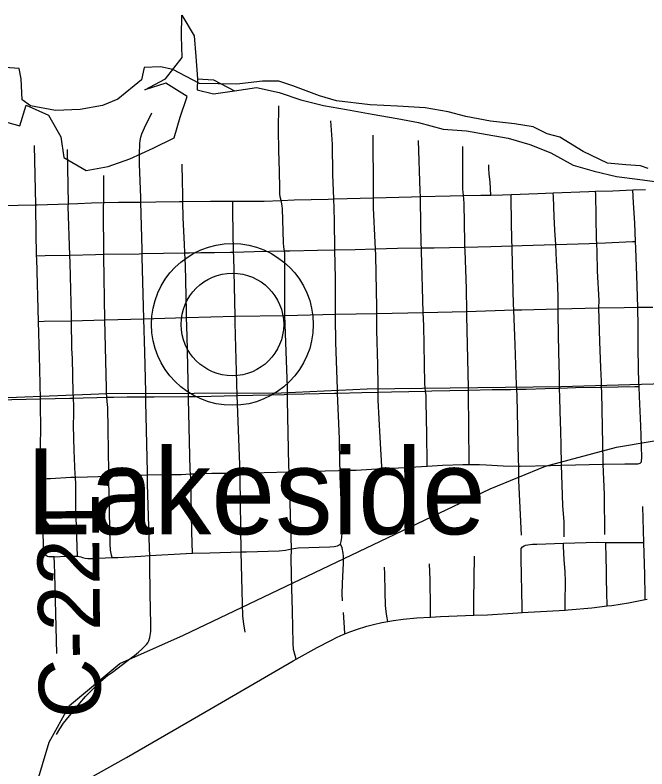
# Model space of a CAD drawing. Extents: x -12 to 34, y 0 to 22.
# Drawn here: x 6.606 to 7.187, y 18.102 to 18.796 of the extents above; entities that cross this region are included whole.
import ezdxf

# ---------------------------------------------------------------- set-up
doc = ezdxf.new("R2010")
doc.units = 0
for name, color, linetype in [('GM_X_Airport_Location_Class_2', 7, 'Continuous'), ('GM_X_Corporation', 7, 'Continuous'), ('GM_X_County_Road', 7, 'Continuous'), ('GM_X_Interstate_Location', 7, 'Continuous'), ('GM_X_Major_Lake', 7, 'Continuous'), ('GM_X_Major_River', 7, 'Continuous'), ('GM_X_Minor_River', 7, 'Continuous'), ('GM_X_Section_Text', 7, 'Continuous'), ('GM_X_Township', 7, 'Continuous'), ('GM_X_Township_Subdivision', 7, 'Continuous')]:
    doc.layers.add(name, color=color, linetype=linetype)

msp = doc.modelspace()

# ---------------------------------------------------------------- linework, layer by layer
at = {"layer": 'GM_X_Airport_Location_Class_2'}
msp.add_lwpolyline([(7.1879, 18.65464), (7.18059, 18.65733), (7.16716, 18.65813), (7.1505, 18.65975), (7.12794, 18.67049), (7.10641, 18.68359), (7.09489, 18.68661), (7.082, 18.69306), (7.0648, 18.69575), (7.04278, 18.69816), (7.02021, 18.70246), (7.00382, 18.70676), (6.9826, 18.71052), (6.95734, 18.71214), (6.93209, 18.71321), (6.9012, 18.71697), (6.88561, 18.72154), (6.8609, 18.73094), (6.84827, 18.73497), (6.83323, 18.73497), (6.80958, 18.73228), (6.7752, 18.73309), (6.75075, 18.74572), (6.7392, 18.7484), (6.72442, 18.7476), (6.72174, 18.73631), (6.69998, 18.71858), (6.686, 18.71267), (6.66559, 18.70918), (6.64275, 18.7081), (6.61992, 18.7124), (6.61213, 18.71805), (6.61105, 18.73739), (6.60944, 18.74679), (6.58768, 18.7484)], dxfattribs=at)
msp.add_lwpolyline([(7.1879, 18.65464), (7.18059, 18.65733), (7.16716, 18.65813), (7.1505, 18.65975), (7.12794, 18.67049), (7.10641, 18.68359), (7.09489, 18.68661), (7.082, 18.69306), (7.0648, 18.69575), (7.04278, 18.69816), (7.02021, 18.70246), (7.00382, 18.70676), (6.9826, 18.71052), (6.95734, 18.71214), (6.93209, 18.71321), (6.9012, 18.71697), (6.88561, 18.72154), (6.8609, 18.73094), (6.84827, 18.73497), (6.83323, 18.73497), (6.80958, 18.73228), (6.7752, 18.73309), (6.75075, 18.74572), (6.7392, 18.7484), (6.72442, 18.7476), (6.72174, 18.73631), (6.69998, 18.71858), (6.686, 18.71267), (6.66559, 18.70918), (6.64275, 18.7081), (6.61992, 18.7124), (6.61213, 18.71805), (6.61105, 18.73739), (6.60944, 18.74679), (6.58768, 18.7484)], dxfattribs=at)
at = {"layer": 'GM_X_Corporation'}
for points in [[(4.21516, 16.89608), (4.31222, 16.96474), (4.74688, 17.31604), (5.03809, 17.55354), (5.18709, 17.66982), (5.65945, 18.04091), (6.05453, 18.35511), (6.09781, 18.38665), (6.1312, 18.40211), (6.16953, 18.40953), (6.55349, 18.44232), (6.69012, 18.44788), (6.85026, 18.4485), (6.9294, 18.45221), (7.10746, 18.45407), (7.25585, 18.4584), (7.28615, 18.45159), (7.37827, 18.44726), (7.7344, 18.45716)], [(5.81508, 17.10766), (6.21975, 17.27361), (6.42432, 17.35397), (6.50615, 17.4016), (6.55673, 17.45964), (6.585, 17.51471), (6.60508, 17.56754), (6.61624, 17.62558), (6.61996, 17.67395), (6.61773, 18.0624), (6.63707, 18.12714), (6.65567, 18.16062), (6.70179, 18.19932), (6.76056, 18.22536), (7.04254, 18.36006), (7.09324, 18.38108), (7.15878, 18.3984), (7.22061, 18.40892), (7.27873, 18.40706), (7.57179, 18.3347), (7.6466, 18.33222), (7.73625, 18.33717), (7.85249, 18.35139), (8.03302, 18.37675)]]:
    msp.add_lwpolyline(points, dxfattribs=at)
at = {"layer": 'GM_X_Interstate_Location'}
for radius in [0.0744, 0.04716]:
    msp.add_circle((6.80544, 18.51131), radius, dxfattribs=at)
at = {"layer": 'GM_X_Major_Lake'}
for points in [[(6.86405, 18.20332), (6.8833, 18.2141), (6.89609, 18.22069), (6.9018, 18.22354), (6.90739, 18.22603), (6.9088, 18.2266), (6.91348, 18.22852), (6.91957, 18.23063), (6.92901, 18.23361), (6.93534, 18.23535), (6.94292, 18.23709), (6.94824, 18.2381), (6.95365, 18.23892), (6.96252, 18.24008), (6.97493, 18.24128), (6.9876, 18.242), (6.99668, 18.24251), (7.02732, 18.24377), (7.04012, 18.24429), (7.06802, 18.24598), (7.07183, 18.2462), (7.11155, 18.24858), (7.11417, 18.24874), (7.13582, 18.25063), (7.15019, 18.25238), (7.15428, 18.25288), (7.16959, 18.25536), (7.18508, 18.25819), (7.18677, 18.25851)], [(6.65922, 18.08561), (6.70793, 18.11308), (6.78602, 18.15808), (6.86128, 18.20177), (6.86405, 18.20332)]]:
    msp.add_lwpolyline(points, dxfattribs=at)
at = {"layer": 'GM_X_Major_River'}
for p, q in [((6.62461, 18.62131), (6.62348, 18.67589)), ((6.65458, 18.62239), (6.65386, 18.6721)), ((7.17353, 18.63503), (7.18535, 18.63547)), ((6.89874, 18.62674), (6.93514, 18.6278)), ((6.59471, 18.6208), (6.60833, 18.62101)), ((6.60833, 18.62101), (6.62461, 18.62131)), ((6.72255, 18.57649), (6.76178, 18.57711)), ((6.98098, 18.52232), (7.02089, 18.52336)), ((7.02089, 18.52336), (7.06422, 18.52468)), ((7.10509, 18.52569), (7.14253, 18.52664)), ((7.17832, 18.52712), (7.1922, 18.52723)), ((6.68808, 18.51548), (6.72391, 18.51638)), ((6.76327, 18.51775), (6.8079, 18.51882)), ((6.8079, 18.51882), (6.85377, 18.51966)), ((6.85377, 18.51966), (6.90015, 18.52074)), ((6.90015, 18.52074), (6.93824, 18.52149)), ((6.93824, 18.52149), (6.98098, 18.52232)), ((6.65752, 18.51477), (6.68808, 18.51548)), ((6.58207, 18.4419), (6.62904, 18.4429)), ((6.81248, 18.37454), (6.80986, 18.44596)), ((7.10802, 18.38189), (7.14644, 18.38265)), ((7.18386, 18.31069), (7.18272, 18.34391))]:
    msp.add_line(p, q, dxfattribs=at)
for points in [[(6.85037, 18.62537), (6.84949, 18.62855), (6.84905, 18.63161), (6.84892, 18.63659), (6.84872, 18.65231), (6.84812, 18.67127), (6.84791, 18.69021), (6.84807, 18.71227)], [(6.72129, 18.62392), (6.72118, 18.628), (6.72001, 18.65881), (6.71991, 18.66814), (6.72022, 18.67744), (6.72054, 18.68052), (6.72116, 18.68354), (6.72201, 18.68651), (6.72457, 18.69216), (6.73145, 18.70608)], [(6.89874, 18.62674), (6.89775, 18.64924), (6.89746, 18.67707), (6.89605, 18.69865)], [(6.93514, 18.6278), (6.93504, 18.63475), (6.93475, 18.68552)], [(6.97827, 18.62901), (6.97815, 18.63386), (6.9766, 18.68044)], [(7.01799, 18.62981), (7.01761, 18.63296), (7.01748, 18.63547), (7.01733, 18.67496)], [(6.75989, 18.62448), (6.75984, 18.6309), (6.75958, 18.64324), (6.75915, 18.65868)], [(7.04296, 18.63038), (7.04273, 18.63619), (7.04248, 18.64242), (7.04144, 18.64945), (7.04111, 18.65507), (7.04124, 18.65827)], [(6.6871, 18.62349), (6.68709, 18.62998), (6.68713, 18.64824)], [(7.1005, 18.63234), (7.13335, 18.63363), (7.13949, 18.63383)], [(7.13949, 18.63383), (7.15539, 18.63437), (7.17353, 18.63503)], [(7.14053, 18.58602), (7.14039, 18.58943), (7.13954, 18.63103), (7.13949, 18.63383)], [(7.17607, 18.58764), (7.17561, 18.6046), (7.17432, 18.62316), (7.17353, 18.63503)], [(6.93514, 18.6278), (6.97, 18.62884), (6.97827, 18.62901)], [(6.937, 18.58088), (6.93676, 18.58675), (6.93534, 18.61859), (6.93514, 18.6278)], [(6.97827, 18.62901), (7.00564, 18.62957), (7.01799, 18.62981)], [(6.97926, 18.58166), (6.9791, 18.58531), (6.97832, 18.62487), (6.97827, 18.62901)], [(7.01799, 18.62981), (7.03394, 18.63013), (7.04296, 18.63038)], [(7.01926, 18.58239), (7.01909, 18.58662), (7.01847, 18.62264), (7.01822, 18.6268), (7.01799, 18.62981)], [(7.04296, 18.63038), (7.05379, 18.63068), (7.06166, 18.63095)], [(7.06166, 18.63095), (7.08631, 18.63179), (7.1005, 18.63234)], [(7.06257, 18.58353), (7.06247, 18.58747), (7.06176, 18.62582), (7.06172, 18.62816), (7.06166, 18.63095)], [(7.10285, 18.58495), (7.10193, 18.59817), (7.10137, 18.61056), (7.10064, 18.62866), (7.1005, 18.63234)], [(6.62461, 18.62131), (6.62603, 18.62133), (6.65458, 18.62239)], [(6.62542, 18.57443), (6.62467, 18.61813), (6.62461, 18.62131)], [(6.65589, 18.57515), (6.65456, 18.61985), (6.65458, 18.62239)], [(6.65458, 18.62239), (6.66335, 18.62269), (6.67572, 18.62325), (6.6871, 18.62349)], [(6.6873, 18.57588), (6.68699, 18.61689), (6.68696, 18.6202), (6.6871, 18.62349)], [(6.6871, 18.62349), (6.70071, 18.62378), (6.71949, 18.62387), (6.72129, 18.62392)], [(6.72129, 18.62392), (6.73513, 18.62406), (6.7569, 18.62445), (6.75989, 18.62448)], [(6.72255, 18.57649), (6.72249, 18.58022), (6.72129, 18.62392)], [(6.75989, 18.62448), (6.7852, 18.62474), (6.80582, 18.62468)], [(6.76178, 18.57711), (6.76145, 18.58504), (6.76012, 18.60935), (6.75989, 18.62448)], [(6.80582, 18.62468), (6.83479, 18.62484), (6.85037, 18.62537)], [(6.80656, 18.57787), (6.80589, 18.61493), (6.80582, 18.62468)], [(6.85037, 18.62537), (6.86223, 18.62579), (6.89336, 18.62656), (6.89874, 18.62674)], [(6.85332, 18.57892), (6.85283, 18.58232), (6.8525, 18.58682), (6.85154, 18.61768), (6.8513, 18.62001), (6.85099, 18.62226), (6.85037, 18.62537)], [(6.89966, 18.57992), (6.89958, 18.58132), (6.89927, 18.60602), (6.89912, 18.61837), (6.89874, 18.62674)], [(7.10285, 18.58495), (7.13354, 18.58567), (7.14053, 18.58602)], [(7.14053, 18.58602), (7.14842, 18.58641), (7.17323, 18.58751), (7.17607, 18.58764)], [(7.14253, 18.52664), (7.14263, 18.53344), (7.14132, 18.56019), (7.14078, 18.57812), (7.14053, 18.58602)], [(7.17832, 18.52712), (7.17745, 18.55628), (7.17653, 18.58108), (7.17607, 18.58764)], [(6.80656, 18.57787), (6.82558, 18.57848), (6.85332, 18.57892)], [(6.85332, 18.57892), (6.85828, 18.57903), (6.88364, 18.57958), (6.89966, 18.57992)], [(6.85377, 18.51966), (6.85376, 18.57308), (6.85356, 18.57619), (6.85332, 18.57892)], [(6.89966, 18.57992), (6.91819, 18.58032), (6.937, 18.58088)], [(6.90015, 18.52074), (6.90034, 18.55362), (6.89966, 18.57992)], [(6.937, 18.58088), (6.95712, 18.58147), (6.97926, 18.58166)], [(6.93824, 18.52149), (6.93828, 18.52722), (6.93774, 18.55808), (6.93719, 18.5749), (6.937, 18.58088)], [(6.97926, 18.58166), (6.99084, 18.58171), (7.01926, 18.58239)], [(6.98098, 18.52232), (6.97939, 18.57869), (6.97926, 18.58166)], [(7.01926, 18.58239), (7.04313, 18.58291), (7.06257, 18.58353)], [(7.02089, 18.52336), (7.0207, 18.54413), (7.01938, 18.57947), (7.01926, 18.58239)], [(7.06257, 18.58353), (7.07198, 18.58383), (7.10212, 18.58493), (7.10285, 18.58495)], [(7.06422, 18.52468), (7.06397, 18.5301), (7.0626, 18.58045), (7.06257, 18.58353)], [(7.10509, 18.52569), (7.10506, 18.53698), (7.10432, 18.55462), (7.1034, 18.57005), (7.10285, 18.58495)], [(6.62542, 18.57443), (6.63341, 18.57462), (6.65589, 18.57515)], [(6.62706, 18.51417), (6.62547, 18.57156), (6.62542, 18.57443)], [(6.65589, 18.57515), (6.67956, 18.57572), (6.6873, 18.57588)], [(6.65752, 18.51477), (6.65745, 18.51883), (6.65614, 18.56812), (6.65589, 18.57515)], [(6.6873, 18.57588), (6.71973, 18.57641), (6.72255, 18.57649)], [(6.68808, 18.51548), (6.68732, 18.5737), (6.6873, 18.57588)], [(6.72391, 18.51638), (6.72254, 18.57315), (6.72255, 18.57649)], [(6.76178, 18.57711), (6.76586, 18.57718), (6.77651, 18.57737), (6.78883, 18.57755), (6.80353, 18.57782), (6.80656, 18.57787)], [(6.76327, 18.51775), (6.76311, 18.52339), (6.76228, 18.56542), (6.76178, 18.57711)], [(6.8079, 18.51882), (6.80663, 18.57381), (6.80656, 18.57787)], [(7.02249, 18.4508), (7.02247, 18.45317), (7.02099, 18.51917), (7.02089, 18.52336)], [(7.06422, 18.52468), (7.07153, 18.52485), (7.10509, 18.52569)], [(7.06686, 18.45167), (7.06656, 18.4559), (7.06539, 18.49249), (7.06422, 18.52468)], [(7.10636, 18.45264), (7.10617, 18.46385), (7.10562, 18.48626), (7.10543, 18.50188), (7.10506, 18.52173), (7.10509, 18.52569)], [(7.14253, 18.52664), (7.16556, 18.52702), (7.17832, 18.52712)], [(7.14499, 18.45376), (7.14477, 18.45904), (7.14417, 18.47151), (7.14333, 18.49574), (7.14253, 18.52664)], [(7.1794, 18.45416), (7.1793, 18.4576), (7.17893, 18.47138), (7.17857, 18.48958), (7.17856, 18.51089), (7.17835, 18.52526), (7.17832, 18.52712)], [(6.72391, 18.51638), (6.73331, 18.51664), (6.76327, 18.51775)], [(6.72589, 18.4448), (6.72576, 18.44928), (6.72502, 18.48594), (6.72391, 18.51638)], [(6.76494, 18.44509), (6.76378, 18.50069), (6.76327, 18.51775)], [(6.80986, 18.44596), (6.80825, 18.50113), (6.80793, 18.51332), (6.8079, 18.51882)], [(6.85611, 18.44706), (6.85598, 18.45343), (6.85377, 18.51966)], [(6.90214, 18.44811), (6.90199, 18.45179), (6.90043, 18.49487), (6.90018, 18.51733), (6.90015, 18.52074)], [(6.93957, 18.44899), (6.93954, 18.45491), (6.93923, 18.47429), (6.93826, 18.50614), (6.93824, 18.52149)], [(6.98306, 18.45007), (6.98284, 18.45285), (6.98255, 18.45694), (6.98154, 18.51028), (6.98098, 18.52232)], [(6.62706, 18.51417), (6.63226, 18.51427), (6.65752, 18.51477)], [(6.62904, 18.4429), (6.62841, 18.46995), (6.62799, 18.4821), (6.62706, 18.51417)], [(6.65945, 18.44353), (6.65913, 18.44861), (6.65837, 18.47996), (6.65789, 18.48911), (6.65752, 18.51477)], [(6.6901, 18.44428), (6.6898, 18.44825), (6.68959, 18.45282), (6.68808, 18.51548)], [(7.10636, 18.45264), (7.12087, 18.45319), (7.14366, 18.45374), (7.14499, 18.45376)], [(7.14499, 18.45376), (7.16019, 18.45393), (7.17544, 18.45411), (7.1794, 18.45416)], [(7.14644, 18.38265), (7.14635, 18.38506), (7.14513, 18.44894), (7.14499, 18.45376)], [(7.18111, 18.38434), (7.18155, 18.38499), (7.18171, 18.38584), (7.18189, 18.38871), (7.18151, 18.39972), (7.18114, 18.41791), (7.17967, 18.44493), (7.1794, 18.45416)], [(6.80986, 18.44596), (6.85297, 18.447), (6.85611, 18.44706)], [(6.85611, 18.44706), (6.87141, 18.44739), (6.89945, 18.44802), (6.90214, 18.44811)], [(6.85757, 18.37577), (6.85733, 18.38147), (6.85617, 18.44164), (6.85611, 18.44706)], [(6.90214, 18.44811), (6.92444, 18.44857), (6.93957, 18.44899)], [(6.90439, 18.37711), (6.90426, 18.38355), (6.90383, 18.40596), (6.90214, 18.44811)], [(6.94284, 18.37875), (6.94278, 18.38076), (6.94124, 18.40737), (6.93954, 18.44153), (6.93957, 18.44899)], [(6.93957, 18.44899), (6.95169, 18.44933), (6.96762, 18.44969), (6.98306, 18.45007)], [(6.98306, 18.45007), (6.98875, 18.45022), (7.02183, 18.45079), (7.02249, 18.4508)], [(6.98462, 18.38103), (6.98457, 18.38431), (6.98415, 18.41015), (6.98377, 18.44002), (6.98348, 18.44584), (6.98306, 18.45007)], [(7.02307, 18.38242), (7.02305, 18.38513), (7.02246, 18.44791), (7.02249, 18.4508)], [(7.02249, 18.4508), (7.04425, 18.45134), (7.06134, 18.45153), (7.06686, 18.45167)], [(7.06686, 18.45167), (7.07567, 18.4519), (7.09294, 18.45245), (7.10636, 18.45264)], [(7.0687, 18.38096), (7.06861, 18.38667), (7.06722, 18.44536), (7.06686, 18.45167)], [(7.10802, 18.38189), (7.10772, 18.40052), (7.10746, 18.41276), (7.10682, 18.43149), (7.10654, 18.444), (7.10636, 18.45264)], [(6.62997, 18.36939), (6.62942, 18.37383), (6.62903, 18.37899), (6.62893, 18.38484), (6.62903, 18.40312), (6.62916, 18.41277), (6.62904, 18.44036), (6.62904, 18.4429)], [(6.62904, 18.4429), (6.65591, 18.44347), (6.65945, 18.44353)], [(6.66103, 18.37085), (6.66087, 18.37339), (6.65993, 18.39533), (6.65936, 18.41844), (6.6596, 18.42868), (6.65976, 18.43621), (6.65945, 18.44353)], [(6.65945, 18.44353), (6.66833, 18.44372), (6.68072, 18.44396), (6.6901, 18.44428)], [(6.6901, 18.44428), (6.69619, 18.44442), (6.70854, 18.44463), (6.72589, 18.4448)], [(6.69177, 18.37185), (6.69166, 18.37566), (6.69119, 18.41491), (6.69078, 18.43494), (6.6904, 18.4404), (6.6901, 18.44428)], [(6.72589, 18.4448), (6.73339, 18.44487), (6.76494, 18.44509)], [(6.7273, 18.37285), (6.72722, 18.37564), (6.72595, 18.43975), (6.72589, 18.4448)], [(6.76494, 18.44509), (6.77397, 18.44515), (6.80986, 18.44596)], [(6.76689, 18.37376), (6.76672, 18.37756), (6.76499, 18.44301), (6.76494, 18.44509)], [(7.14644, 18.38265), (7.14734, 18.38263), (7.1663, 18.38303), (7.17835, 18.38321), (7.1794, 18.38333), (7.18034, 18.38366), (7.18111, 18.38434)], [(6.90439, 18.37711), (6.91931, 18.37728), (6.94284, 18.37875)], [(6.94284, 18.37875), (6.9582, 18.37955), (6.98462, 18.38103)], [(6.98462, 18.38103), (6.99855, 18.38181), (7.0172, 18.38241), (7.02307, 18.38242)], [(7.02307, 18.38242), (7.03273, 18.38242), (7.03893, 18.38201), (7.05445, 18.38112), (7.0687, 18.38096)], [(7.0687, 18.38096), (7.06998, 18.38094), (7.09794, 18.38158), (7.10802, 18.38189)], [(7.0714, 18.31759), (7.06899, 18.3678), (7.06884, 18.37497), (7.0687, 18.38096)], [(7.11059, 18.31593), (7.11066, 18.32982), (7.10943, 18.34479), (7.10857, 18.3637), (7.10802, 18.38189)], [(7.14793, 18.31822), (7.14753, 18.35477), (7.14644, 18.38265)], [(6.62997, 18.36939), (6.635, 18.3696), (6.63812, 18.36973), (6.65678, 18.37072), (6.66103, 18.37085)], [(6.66103, 18.37085), (6.67208, 18.3712), (6.69177, 18.37185)], [(6.66308, 18.29814), (6.66155, 18.34294), (6.66133, 18.36445), (6.66103, 18.37085)], [(6.69177, 18.37185), (6.69998, 18.37208), (6.7273, 18.37285)], [(6.69472, 18.29678), (6.69431, 18.29903), (6.69344, 18.30373), (6.69292, 18.30948), (6.69187, 18.3687), (6.69177, 18.37185)], [(6.7273, 18.37285), (6.74295, 18.37321), (6.75835, 18.37341), (6.76689, 18.37376)], [(6.72946, 18.29879), (6.72914, 18.3054), (6.72743, 18.36462), (6.7273, 18.37285)], [(6.76689, 18.37376), (6.77286, 18.37396), (6.78641, 18.37435), (6.80888, 18.37451), (6.81248, 18.37454)], [(6.76885, 18.30092), (6.76818, 18.32013), (6.76743, 18.35391), (6.76707, 18.36984), (6.76689, 18.37376)], [(6.81248, 18.37454), (6.83479, 18.37507), (6.85757, 18.37577)], [(6.81361, 18.302), (6.81265, 18.3697), (6.81248, 18.37454)], [(6.85757, 18.37577), (6.87231, 18.37623), (6.89077, 18.37668), (6.90314, 18.3771), (6.90439, 18.37711)], [(6.8597, 18.30489), (6.85821, 18.35769), (6.85757, 18.37577)], [(6.90486, 18.30931), (6.9056, 18.31152), (6.90609, 18.31544), (6.90633, 18.3195), (6.90608, 18.33548), (6.90444, 18.37153), (6.90439, 18.37711)], [(6.64152, 18.29745), (6.63822, 18.29745), (6.6366, 18.29766), (6.63551, 18.29799), (6.63456, 18.29856), (6.63343, 18.29953), (6.63261, 18.30044), (6.63198, 18.30153), (6.63166, 18.30271), (6.63159, 18.3049), (6.63088, 18.36028), (6.63047, 18.36546), (6.62997, 18.36939)], [(6.8597, 18.30489), (6.86582, 18.30571), (6.89505, 18.30685), (6.89909, 18.30698), (6.90204, 18.30759), (6.90486, 18.30931)], [(6.90678, 18.257), (6.90649, 18.26353), (6.90659, 18.27291), (6.90757, 18.2917), (6.90752, 18.29793), (6.90734, 18.30104), (6.90634, 18.30587), (6.90486, 18.30931)], [(7.07105, 18.30534), (7.07233, 18.30663), (7.07371, 18.30761), (7.07508, 18.30828), (7.07722, 18.30872), (7.08143, 18.30906), (7.08529, 18.30926), (7.10979, 18.30997)], [(7.10979, 18.30997), (7.14108, 18.31088), (7.14881, 18.31084)], [(7.11155, 18.24858), (7.11158, 18.25536), (7.11169, 18.27477), (7.11147, 18.28415), (7.11061, 18.29482), (7.10992, 18.30742), (7.10979, 18.30997)], [(7.14881, 18.31084), (7.1774, 18.31069), (7.18386, 18.31069)], [(7.15019, 18.25238), (7.15001, 18.25608), (7.14978, 18.26091), (7.14901, 18.30075), (7.14891, 18.30586), (7.14881, 18.31084)], [(7.18508, 18.25819), (7.18503, 18.2619), (7.18475, 18.28088), (7.18386, 18.31069)], [(6.72946, 18.29879), (6.76299, 18.30069), (6.76885, 18.30092)], [(6.76885, 18.30092), (6.7846, 18.30123), (6.81361, 18.302)], [(6.81361, 18.302), (6.81842, 18.30224), (6.8485, 18.303), (6.85427, 18.30358), (6.8597, 18.30489)], [(6.81732, 18.22819), (6.8159, 18.23587), (6.81503, 18.24295), (6.81443, 18.26618), (6.81361, 18.302)], [(6.86405, 18.20332), (6.86316, 18.20689), (6.86177, 18.21243), (6.8613, 18.21811), (6.86073, 18.24763), (6.86021, 18.26878), (6.85952, 18.29552), (6.8597, 18.30489)], [(7.07183, 18.2462), (7.07176, 18.25083), (7.0711, 18.29554), (7.07106, 18.30288), (7.07105, 18.30534)], [(6.64152, 18.29745), (6.65289, 18.29802), (6.66308, 18.29814)], [(6.644, 18.20869), (6.64225, 18.2819), (6.64188, 18.29098), (6.64152, 18.29745)], [(6.6436, 18.13395), (6.64672, 18.13934), (6.65027, 18.14443), (6.6583, 18.15472), (6.66517, 18.16302), (6.67027, 18.16893), (6.67729, 18.17611), (6.6824, 18.18122), (6.6907, 18.18841), (6.69506, 18.19158), (6.71235, 18.20472), (6.71547, 18.20688), (6.71912, 18.20984), (6.72214, 18.21267), (6.72422, 18.21475), (6.72527, 18.21571), (6.72644, 18.21698), (6.72752, 18.2185), (6.72844, 18.22021), (6.72949, 18.22325), (6.73028, 18.22879), (6.73045, 18.23518), (6.7298, 18.26375), (6.7296, 18.29057), (6.72946, 18.29879)], [(6.66308, 18.29814), (6.66452, 18.2979), (6.66599, 18.29756), (6.66774, 18.29694), (6.67, 18.29637), (6.67255, 18.29615), (6.6768, 18.29608), (6.69472, 18.29678)], [(6.69472, 18.29678), (6.70021, 18.297), (6.72121, 18.29805), (6.72946, 18.29879)], [(7.02732, 18.24377), (7.02736, 18.24741), (7.02745, 18.25751), (7.02815, 18.29806)], [(6.94824, 18.2381), (6.9474, 18.2428), (6.94671, 18.24728), (6.94636, 18.2528), (6.94586, 18.26543), (6.94548, 18.28174), (6.94538, 18.28789)], [(6.9876, 18.242), (6.9876, 18.24622), (6.9876, 18.25077), (6.98741, 18.27669), (6.98664, 18.29115)], [(6.9088, 18.2266), (6.90844, 18.23238), (6.90754, 18.24644)]]:
    msp.add_lwpolyline(points, dxfattribs=at)
at = {"layer": 'GM_X_Minor_River'}
for points in [[(6.59087, 18.69938), (6.60985, 18.69406), (6.61592, 18.71306), (6.63641, 18.70395), (6.6478, 18.68381), (6.65046, 18.66481), (6.67096, 18.65304), (6.69107, 18.65646), (6.71118, 18.66368), (6.73243, 18.67356), (6.75179, 18.68306), (6.75748, 18.70206), (6.76393, 18.72105), (6.74419, 18.73321), (6.72484, 18.72713), (6.74381, 18.73739), (6.75937, 18.75677), (6.75861, 18.77652), (6.75898, 18.7959), (6.77037, 18.77691), (6.77189, 18.75791), (6.77341, 18.73739), (6.77303, 18.72725)], [(6.59087, 18.69938), (6.60985, 18.69406), (6.61592, 18.71306), (6.63641, 18.70395), (6.6478, 18.68381), (6.65046, 18.66481), (6.67096, 18.65304), (6.69107, 18.65646), (6.71118, 18.66368), (6.73243, 18.67356), (6.75179, 18.68306), (6.75748, 18.70206), (6.76393, 18.72105), (6.74419, 18.73321), (6.72484, 18.72713), (6.74381, 18.73739), (6.75937, 18.75677), (6.75861, 18.77652), (6.75898, 18.7959), (6.77037, 18.77691), (6.77189, 18.75791), (6.77341, 18.73739), (6.78814, 18.73626)], [(6.78814, 18.73626), (6.80738, 18.72626), (6.82753, 18.72931), (6.84844, 18.72475), (6.86822, 18.71791), (6.88913, 18.71259), (6.91042, 18.70918), (6.934, 18.70462), (6.95681, 18.70082), (6.97659, 18.69702), (6.9994, 18.69094), (7.0207, 18.68943), (7.0397, 18.68601), (7.0591, 18.68259), (7.07887, 18.67689), (7.09827, 18.66929), (7.1188, 18.6579), (7.13819, 18.6522), (7.15872, 18.64726), (7.17812, 18.64498), (7.19865, 18.64233)], [(6.77303, 18.72725), (6.78798, 18.7236), (6.80738, 18.72626), (6.82753, 18.72931), (6.84844, 18.72475), (6.86822, 18.71791), (6.88913, 18.71259), (6.91042, 18.70918), (6.934, 18.70462), (6.95681, 18.70082), (6.97659, 18.69702), (6.9994, 18.69094), (7.0207, 18.68943), (7.0397, 18.68601), (7.0591, 18.68259), (7.07887, 18.67689), (7.09827, 18.66929), (7.1188, 18.6579), (7.13819, 18.6522), (7.15872, 18.64726), (7.17812, 18.64498), (7.19865, 18.64233)]]:
    msp.add_lwpolyline(points, dxfattribs=at)
at = {"layer": 'GM_X_Township'}
for points in [[(6.86405, 18.20332), (6.8833, 18.2141), (6.89609, 18.22069), (6.9018, 18.22354), (6.90739, 18.22603), (6.9088, 18.2266), (6.91348, 18.22852), (6.91957, 18.23063), (6.92901, 18.23361), (6.93534, 18.23535), (6.94292, 18.23709), (6.94824, 18.2381), (6.95365, 18.23892), (6.96252, 18.24008), (6.97493, 18.24128), (6.9876, 18.242), (6.99668, 18.24251), (7.02732, 18.24377), (7.04012, 18.24429), (7.06802, 18.24598), (7.07183, 18.2462), (7.11155, 18.24858), (7.11417, 18.24874), (7.13582, 18.25063), (7.15019, 18.25238), (7.15428, 18.25288), (7.16959, 18.25536), (7.18508, 18.25819), (7.18677, 18.25851)], [(6.60709, 18.05699), (6.65922, 18.08561), (6.70793, 18.11308), (6.78602, 18.15808), (6.86128, 18.20177), (6.86405, 18.20332)]]:
    msp.add_lwpolyline(points, dxfattribs=at)
at = {"layer": 'GM_X_Township_Subdivision'}
msp.add_line((6.80544, 18.51131), (6.80544, 18.51131), dxfattribs=at)

# ---------------------------------------------------------------- texts
at = {"layer": 'GM_X_County_Road'}
msp.add_text('C-221', height=0.056818, rotation=90.551, dxfattribs=at).set_placement((6.68447, 18.14934))
at = {"layer": 'GM_X_Section_Text'}
msp.add_text('Lakeside', height=0.078977, rotation=0.00001, dxfattribs=at).set_placement((6.61576, 18.31828))

doc.saveas('drawing.dxf')
